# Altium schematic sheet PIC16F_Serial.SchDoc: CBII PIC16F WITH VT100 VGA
size A3; Engineer: SRKH; DocumentNumber: 1; Revision: 1.00; SheetNumber: 1; SheetTotal: 7
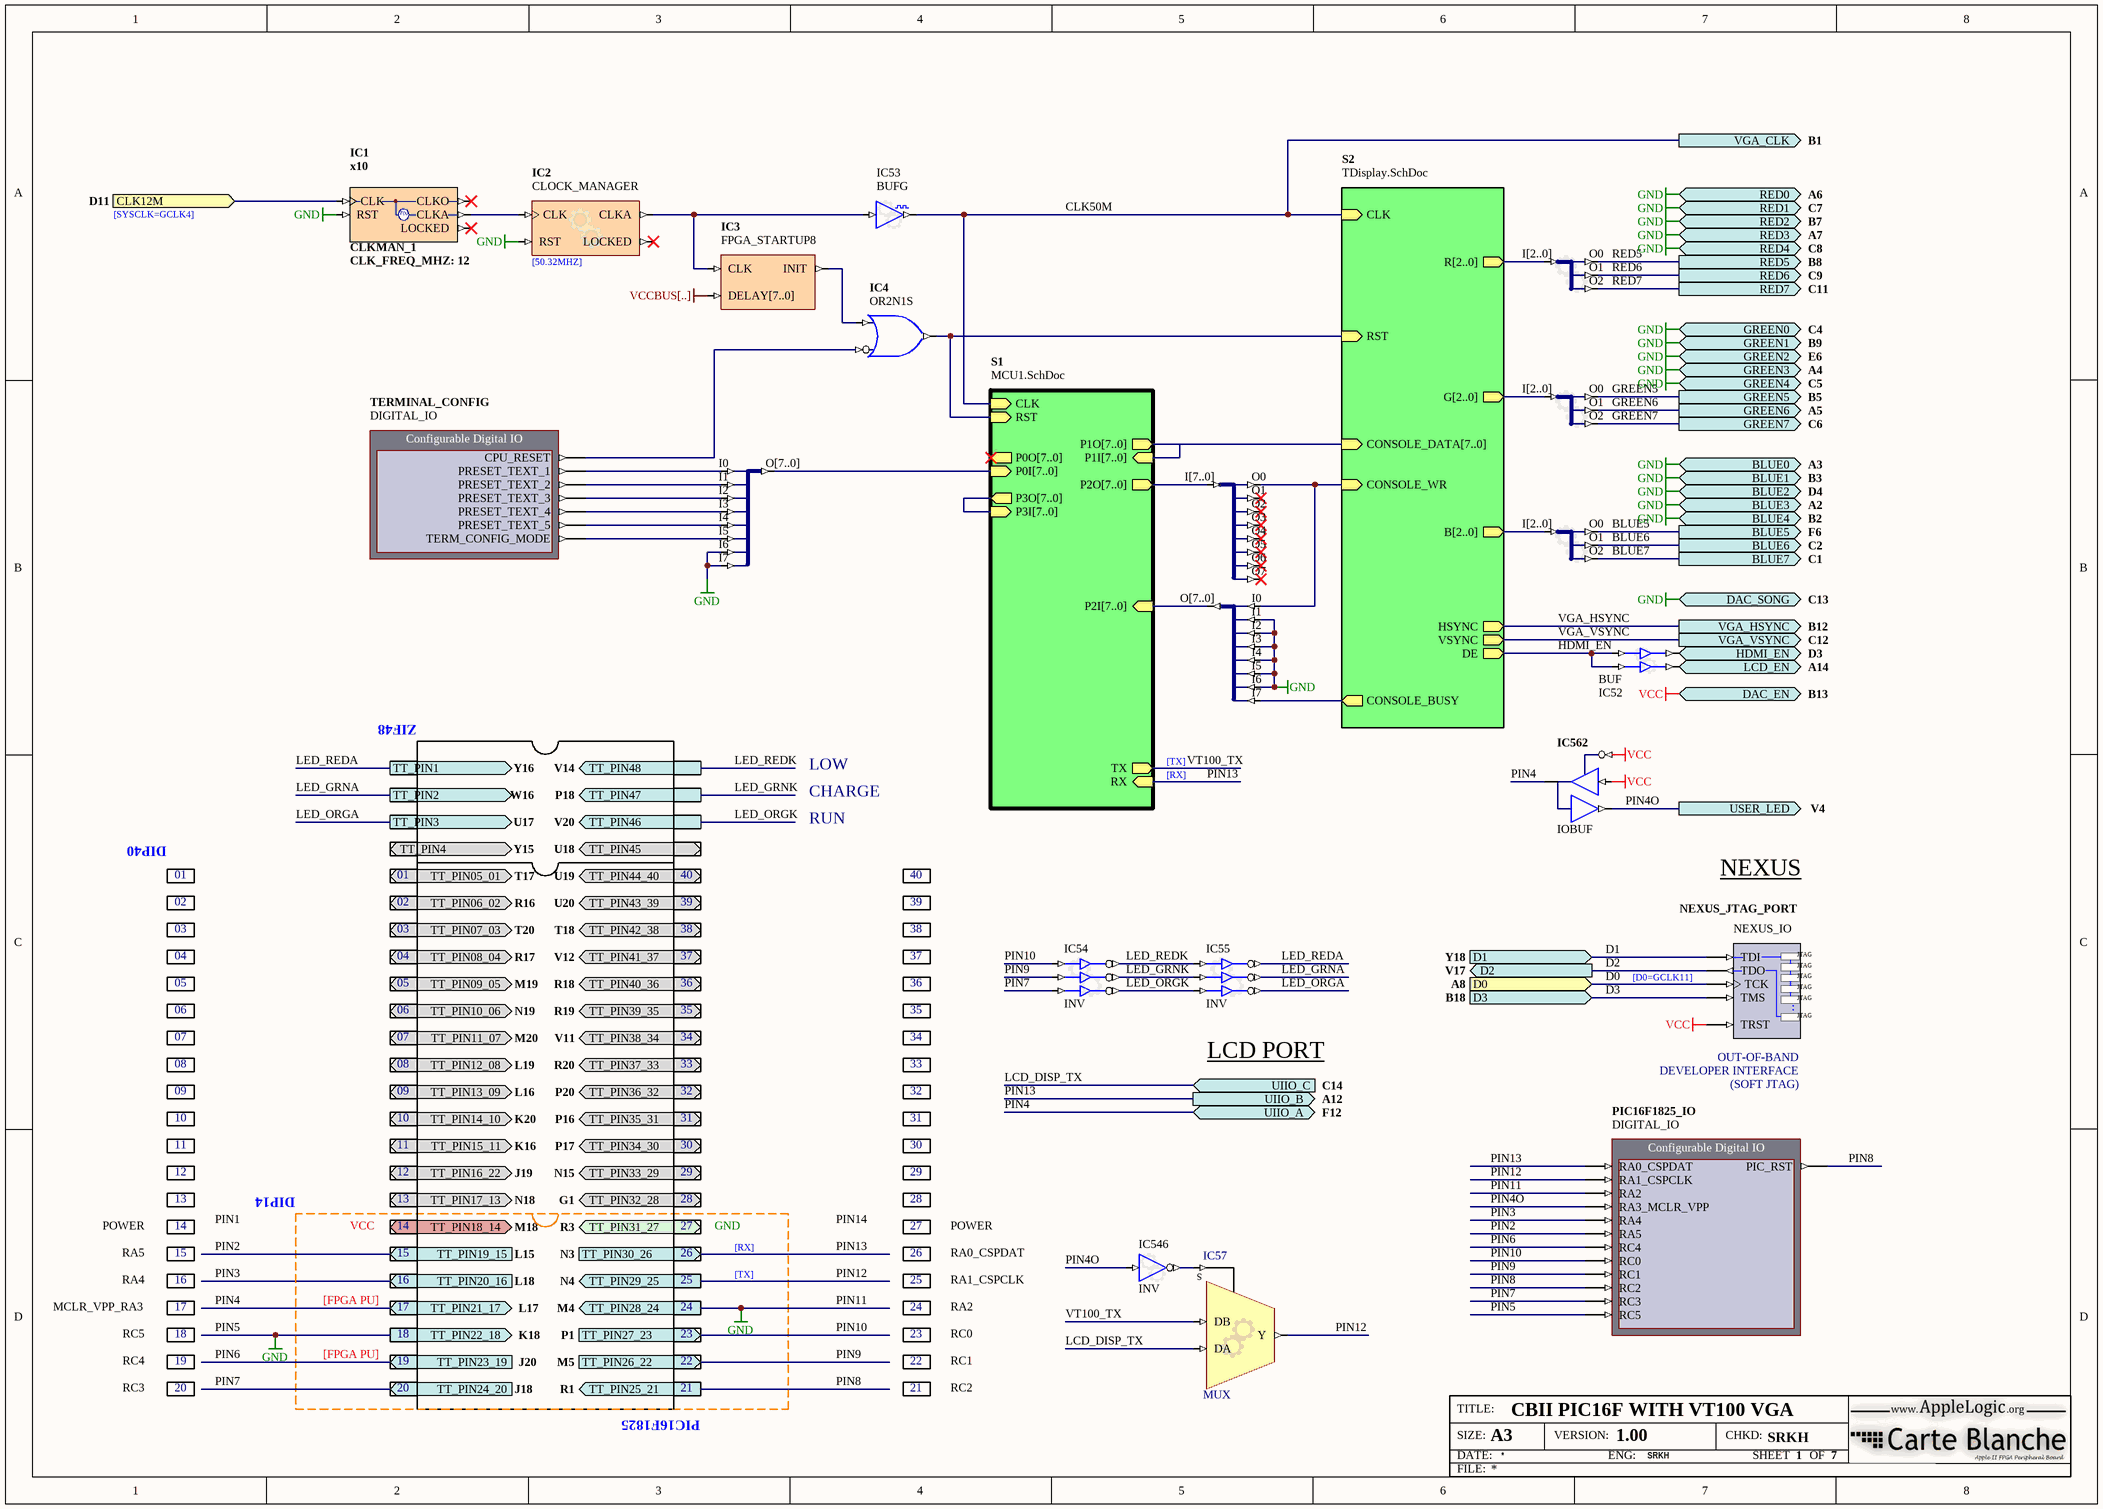
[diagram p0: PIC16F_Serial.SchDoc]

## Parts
IC1  CLKMAN_1  CLK_FREQ_MHZ: 12  ClkA_Operation: x10
IC2  CLOCK_MANAGER
IC3  FPGA_STARTUP8
IC4  OR2N1S
IC5  BUS_JS  (value not drawn)
IC6  BUS_JS  (value not drawn)
IC7  J8B_8S  (value not drawn)
IC8  BUS_JS  (value not drawn)
IC9  J8S_8B  (value not drawn)
IC10  J8S_8B  (value not drawn)
IC52  BUF
IC53  BUFG
IC54  INV
IC55  INV
IC57  MUX
IC546  INV
IC562  IOBUF
NEXUS_JTAG_PORT  NEXUS_IO
PIC16F1825_IO  DIGITAL_IO
TERMINAL_CONFIG  DIGITAL_IO

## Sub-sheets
S1 = MCU1.SchDoc: CLK (in), RST (in), P0O[7..0] (out), P0I[7..0] (in), P1O[7..0] (out), P1I[7..0] (in), P2O[7..0] (out), P2I[7..0] (in), P3O[7..0] (out), P3I[7..0] (in), TX (out), RX (in)
S2 = TDisplay.SchDoc: CLK (in), HSYNC (out), VSYNC (out), R[2..0] (out), G[2..0] (out), B[2..0] (out), CONSOLE_WR (in), CONSOLE_DATA[7..0] (in), CONSOLE_BUSY (out), RST (in), DE (out)

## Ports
BLUE0 (out, see A3), BLUE1 (out, see B3), BLUE2 (out, see D4), BLUE3 (out, see A2), BLUE4 (out, see B2), BLUE5 (out, see F6), BLUE6 (out, see C2), BLUE7 (out, see C1), CLK12M (in, see D11), D0 (in, see A8), D1 (in, see Y18), D2 (out, see V17), D3 (in, see B18), DAC_EN (out, see B13), DAC_SONG (out, see C13), GREEN0 (out, see C4), GREEN1 (out, see B9), GREEN2 (out, see E6), GREEN3 (out, see A4), GREEN4 (out, see C5), GREEN5 (out, see B5), GREEN6 (out, see A5), GREEN7 (out, see C6), HDMI_EN (out, see D3), LCD_EN (out, see A14), RED0 (out, see A6), RED1 (out, see C7), RED2 (out, see B7), RED3 (out, see A7), RED4 (out, see C8), RED5 (out, see B8), RED6 (out, see C9), RED7 (out, see C11), TT_PIN1 (out, see Y16), TT_PIN2 (out, see W16), TT_PIN3 (out, see U17), TT_PIN4 (bidir, see Y15), TT_PIN05_01 (bidir, see T17), TT_PIN06_02 (bidir, see R16), TT_PIN07_03 (bidir, see T20), TT_PIN08_04 (bidir, see R17), TT_PIN09_05 (bidir, see M19), TT_PIN10_06 (bidir, see N19), TT_PIN11_07 (bidir, see M20), TT_PIN12_08 (bidir, see L19), TT_PIN13_09 (bidir, see L16), TT_PIN14_10 (bidir, see K20), TT_PIN15_11 (bidir, see K16), TT_PIN16_22 (bidir, see J19), TT_PIN17_13 (bidir, see N18), TT_PIN18_14 (in, see M18), TT_PIN19_15 (in, see L15), TT_PIN20_16 (in, see L18), TT_PIN21_17 (bidir, see L17), TT_PIN22_18 (out, see K18), TT_PIN23_19 (in, see J20), TT_PIN24_20 (in, see J18), TT_PIN25_21 (out, see R1), TT_PIN26_22 (in, see M5), TT_PIN27_23 (in, see P1), TT_PIN28_24 (out, see M4), TT_PIN29_25 (out, see N4), TT_PIN30_26 (in, see N3), TT_PIN31_27 (in, see R3), TT_PIN32_28 (bidir, see G1), TT_PIN33_29 (bidir, see N15), TT_PIN34_30 (bidir, see P17), TT_PIN35_31 (bidir, see P16), TT_PIN36_32 (bidir, see P20), TT_PIN37_33 (bidir, see R20), TT_PIN38_34 (bidir, see V11), TT_PIN39_35 (bidir, see R19), TT_PIN40_36 (bidir, see R18), TT_PIN41_37 (bidir, see V12), TT_PIN42_38 (bidir, see T18), TT_PIN43_39 (bidir, see U20), TT_PIN44_40 (bidir, see U19), TT_PIN45 (in, see U18), TT_PIN46 (out, see V20), TT_PIN47 (out, see P18), TT_PIN48 (out, see V14), UIIO_A (bidir, see F12), UIIO_B (out, see A12), UIIO_C (in, see C14), USER_LED (out, see V4), VGA_CLK (out, see B1), VGA_HSYNC (out, see B12), VGA_VSYNC (out, see C12)

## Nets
PIN11: IC1.RST IC2.RST IC9.I1 IC9.I2 IC9.I3 IC9.I4 IC9.I5 IC9.I6 IC10.I6 IC10.I7 PIC16F1825_IO.RA2 PIC16F1825_IO.RC5 ; port DAC_SONG, port BLUE2, port BLUE3, port BLUE4, port BLUE0, port BLUE1, port RED2, port RED3, port RED4, port RED0, port RED1, port GREEN2, port GREEN3, port GREEN4, port GREEN0, port GREEN1, port TT_PIN22_18, port TT_PIN28_24  [also labelled GND, PIN5]
VCC: IC562.I IC562.T NEXUS_JTAG_PORT.TRST ; port DAC_EN
VCCBUS[..]: IC3.DELAY[7..0]
BLUE5: IC8.O0 ; port BLUE5
BLUE6: IC8.O1 ; port BLUE6
BLUE7: IC8.O2 ; port BLUE7
CLK12M: IC1.CLK ; port CLK12M
CLK50M: IC53.O ; port VGA_CLK, sheet S1/CLK, sheet S2/CLK
D0: NEXUS_JTAG_PORT.TCK ; port D0
D1: NEXUS_JTAG_PORT.TDI ; port D1
D2: NEXUS_JTAG_PORT.TDO ; port D2
D3: NEXUS_JTAG_PORT.TMS ; port D3
GREEN5: IC6.O0 ; port GREEN5
GREEN6: IC6.O1 ; port GREEN6
GREEN7: IC6.O2 ; port GREEN7
HDMI_EN: IC52.I0 IC52.I1 ; sheet S2/DE
HDMI_EN: IC52.O0 ; port HDMI_EN  [a separate net that carries the same name]
LCD_DISP_TX: IC57.DA ; port UIIO_C
LCD_EN: IC52.O1 ; port LCD_EN
LED_GRNA: IC55.O1 ; port TT_PIN2
LED_GRNK: IC54.O1 IC55.I1 ; port TT_PIN47
LED_ORGA: IC55.O2 ; port TT_PIN3
LED_ORGK: IC54.O2 IC55.I2 ; port TT_PIN46
LED_REDA: IC55.O0 ; port TT_PIN1
LED_REDK: IC54.O0 IC55.I0 ; port TT_PIN48
PIN2: PIC16F1825_IO.RA5 ; port TT_PIN19_15
PIN3: PIC16F1825_IO.RA4 ; port TT_PIN20_16
PIN4: IC562.IO ; port TT_PIN21_17, port UIIO_A
PIN4O: IC546.I IC562.O PIC16F1825_IO.RA3_MCLR_VPP ; port USER_LED
PIN6: PIC16F1825_IO.RC4 ; port TT_PIN23_19
PIN7: IC54.I2 PIC16F1825_IO.RC3 ; port TT_PIN24_20
PIN8: PIC16F1825_IO.PIC_RST PIC16F1825_IO.RC2 ; port TT_PIN25_21
PIN9: IC54.I1 PIC16F1825_IO.RC1 ; port TT_PIN26_22
PIN10: IC54.I0 PIC16F1825_IO.RC0 ; port TT_PIN27_23
PIN12: IC57.Y PIC16F1825_IO.RA1_CSPCLK ; port TT_PIN29_25
PIN13: PIC16F1825_IO.RA0_CSPDAT ; port TT_PIN30_26, port UIIO_B, sheet S1/RX
RED5: IC5.O0 ; port RED5
RED6: IC5.O1 ; port RED6
RED7: IC5.O2 ; port RED7
VGA_HSYNC: port VGA_HSYNC, sheet S2/HSYNC
VGA_VSYNC: port VGA_VSYNC, sheet S2/VSYNC
VT100_TX: IC57.DB ; sheet S1/TX
NetIC1_CLKA: IC1.CLKA IC2.CLK
NetIC2_CLKA: IC2.CLKA IC3.CLK IC53.I
NetIC3_INIT: IC3.INIT IC4.I1
NetIC4_I0: IC4.I0 TERMINAL_CONFIG.CPU_RESET
NetIC4_O: IC4.O ; sheet S1/RST, sheet S2/RST
NetIC7_O0: IC7.O0 IC9.I0 ; sheet S2/CONSOLE_WR
NetIC9_I7: IC9.I7 ; sheet S2/CONSOLE_BUSY
NetIC10_I0: IC10.I0 TERMINAL_CONFIG.PRESET_TEXT_1
NetIC10_I1: IC10.I1 TERMINAL_CONFIG.PRESET_TEXT_2
NetIC10_I2: IC10.I2 TERMINAL_CONFIG.PRESET_TEXT_3
NetIC10_I3: IC10.I3 TERMINAL_CONFIG.PRESET_TEXT_4
NetIC10_I4: IC10.I4 TERMINAL_CONFIG.PRESET_TEXT_5
NetIC10_I5: IC10.I5 TERMINAL_CONFIG.TERM_CONFIG_MODE
NetIC57_S: IC57.S IC546.O

Not connected (* = marked no-connect by the designer): IC1 CLKO* LOCKED*; IC2 LOCKED*; IC5 I[2..0]; IC6 I[2..0]; IC7 I[7..0] O1* O2* O3* O4* O5* O6* O7*; IC8 I[2..0]; IC9 O[7..0]; IC10 O[7..0]

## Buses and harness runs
bus sheet S1/P1I[7..0] = sheet S1/P1O[7..0] = sheet S2/CONSOLE_DATA[7..0]
bus sheet S1/P3I[7..0] = sheet S1/P3O[7..0]

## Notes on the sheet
- [SYSCLK=GCLK4]
- (near IC2) [50.32MHZ]
- ZIF48
- LOW
- [TX]
- [RX]
- DIP40
- RUN
- CHARGE
- 01
- 02
- 40
- 39
- NEXUS
- 03
- 04
- 05
- 38
- 37
- 36
- (near NEXUS_JTAG_PORT) [D0=GCLK11]
- 06
- 07
- 35
- 34
- 08
- 09
- 10
- 33
- 32
- 31
- (near IC55) LCD PORT
- (near NEXUS_JTAG_PORT) DEVELOPER INTERFACE
- (near NEXUS_JTAG_PORT) OUT-OF-BAND
- (SOFT JTAG)
- 11
- 12
- DIP14
- 30
- 29
- POWER
- RA5
- 13
- 14
- 15
- VCC
- 28
- 27
- 26
- GND
- RA0_CSPDAT
- MCLR_VPP_RA3
- RA4
- 16
- 17
- [FPGA PU]
- 25
- 24
- RA1_CSPCLK
- RA2
- RC5
- RC4
- RC3
- 18
- 19
- 20
- 23
- 22
- 21
- RC0
- RC1
- RC2
- PIC16F1825
- Labels drawn without touching a wire or pin: PIN1, PIN14

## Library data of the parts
IC1 = CLKMAN_1: Single Operational Output Clock Manager; Clk_Count: 1
IC2 = CLOCKMANAGER: Configurable Clock Manager; ConfiguratorName: GENERIC_CLOCKMANAGER; ConfigurationParameters: {}Version[1.0]{}Option_Configuration[object _1: TClockManagerPersist / VersionMajor [ 0 / VersionMinor [ 0 / InputFreq [ 120.000000000000000000 / InputName [ 'CLK' / OutputTargets [ < / item / Name [ 'CLKA' / OutFreqMin [ 49.846500000000000000 / OutFreqMax [ 50.853500000000000000 / OutPostDivider [ 1.000000000000000000 / end> / OutputDevices [ < / item / Name [ 'Spartan3AN' / Valid [ True / OutputActuals [ < / item / Name [ 'CLK0' / Multipler [ 1.000000000000000000 / Divider [ 1.000000000000000000 / OutFreq [ 120.000000000000000000 / OutputMap [ 1 / end / item / Name [ 'CLK90' / Multipler [ 1.000000000000000000 / Divider [ 1.000000000000000000 / OutPhase [ 90.000000000000000000 / OutFreq [ 120.000000000000000000 / OutputMap [ 2 / end / item / Name [ 'CLK180' / Multipler [ 1.000000000000000000 / Divider [ 1.000000000000000000 / OutPhase [ 180.000000000000000000 / OutFreq [ 120.000000000000000000 / OutputMap [ 3 / end / item / Name [ 'CLK270' / Multipler [ 1.000000000000000000 / Divider [ 1.000000000000000000 / OutPhase [ 270.000000000000000000 / OutFreq [ 120.000000000000000000 / OutputMap [ 4 / end / item / Name [ 'CLK2X' / Multipler [ 2.000000000000000000 / Divider [ 1.000000000000000000 / OutFreq [ 240.000000000000000000 / OutputMap [ 5 / end / item / Name [ 'CLKDV' / Multipler [ 1.000000000000000000 / Divider [ 16.000000000000000000 / OutFreq [ 7.500000000000000000 / OutputMap [ 6 / end / item / Name [ 'CLK2X180' / Multipler [ 1.000000000000000000 / Divider [ 1.000000000000000000 / OutPhase [ 180.000000000000000000 / OutFreq [ 240.000000000000000000 / OutputMap [ 7 / end / item / Name [ 'CLKFX' / Multipler [ 13.000000000000000000 / Divider [ 31.000000000000000000 / OutFreq [ 50.322580645161290000 / OutputMap [ 0 / end / item / Name [ 'CLKFX180' / Multipler [ 1.000000000000000000 / Divider [ 1.000000000000000000 / OutPhase [ 180.000000000000000000 / OutFreq [ 50.322580645161290000 / OutputMap [ 8 / end> / InternalActuals [ <> / CustomVars [ <> / end> / MinInputFreq [ 1.000000000000000000 / MaxInputFreq [ 280.000000000000000000 / MinOutputFreq [ 18.000000000000000000 / MaxOutputFreq [ 210.000000000000000000 / MaxOutputCount [ 9 / end]{}
IC3 = FPGA_STARTUP8: FPGA Startup With 8 Bit Delay
IC4 = OR2N1S: 2-Input OR Gate with Active Low A Input, Single Pin Version; Xilinx Equivalent: OR2B1; ArchiveName: GENERIC
IC5 IC6 IC8 = BUS_JS: Configurable Bus Joiner/Splitter; ConfiguratorName: GENERIC_BUS_JS; ConfigurationParameters: {}Version[1.1]{}SplitterJoinerType[Splitter]{}SignalCount[3]{}SignalWidth0[1]{}GapBelow0[1000000]{}ConnectionType0[Pin]{}SignalWidth1[1]{}GapBelow1[1000000]{}ConnectionType1[Pin]{}SignalWidth2[1]{}GapBelow2[1000000]{}ConnectionType2[Pin]{}ShowPinNames[True]{}
IC7 = J8B_8S: 8-Bit input bus to 8 single pin outputs; FunctionalClass: Bus Joiner; PortSize: 8; ArchiveName: GENERIC; VHDLIB_SIM: GENERIC_LIB
IC9 = J8S_8B: 8 Single pin inputs to single 8-Bit output bus; FunctionalClass: Bus Joiner; PortSize: 8; ArchiveName: GENERIC; VHDLIB_SIM: GENERIC_LIB
IC10 = J8S_8B: 8 Single pin inputs to single 8-Bit output bus; ArchiveName: GENERIC; VHDLIB_SIM: GENERIC_LIB
IC52 = BUF: Configurable Buffer; ConfiguratorName: GENERIC_BUFFER; ConfigurationParameters: {}Version[1.1]{}SignalCount[2]{}SignalWidth0[1]{}OutputOption0[Normal]{}SignalWidth1[1]{}OutputOption1[Normal]{}EnableMode[None]{}ShowPinNames[False]{}
IC53 = BUFG: Configurable Global Clock Buffer; ConfiguratorName: GENERIC_BUFFER; ConfigurationParameters: {}Version[1.1]{}SignalCount[1]{}SignalWidth0[1]{}OutputOption0[Global Clock]{}EnableMode[None]{}ShowPinNames[False]{}
IC54 IC55 = INV: Configurable Inverter; ConfiguratorName: GENERIC_BUFFER; ConfigurationParameters: {}Version[1.1]{}SignalCount[3]{}SignalWidth0[1]{}OutputOption0[Inverted]{}SignalWidth1[1]{}OutputOption1[Inverted]{}SignalWidth2[1]{}OutputOption2[Inverted]{}EnableMode[None]{}ShowPinNames[False]{}
IC57 = MUX: Configurable Mutliplexer; ConfigurationParameters: {}Version[1.0]{}ShowEnable[False]{}BusInputs[False]{}BusOutputs[False]{}SignalWidth[1]{}Type[Multiplexer]{}RegisterOutputs[False]{}NegativeClockEdge[False]{}ShowPinNames[True]{}InvertSingleSignal[False]{}SignalCount[2]{}Invert0[False]{}Invert1[False]{}; ConfiguratorName: GENERIC_MULTIPLEXER
IC546 = INV: Configurable Inverter; ConfiguratorName: GENERIC_BUFFER; ConfigurationParameters: {}Version[1.1]{}SignalCount[1]{}SignalWidth0[1]{}OutputOption0[Inverted]{}EnableMode[None]{}ShowPinNames[False]{}
IC562 = IOBUF: Input/Output Buffer; Enable: Low; Control: Common Control T; ArchiveName: GENERIC; VHDLIB_SIM: GENERIC_LIB
NEXUS_JTAG_PORT = NEXUS_JTAG_PORT: Soft Nexus-Chain Connector; NEXUS_JTAG_CONNECTOR: True
PIC16F1825_IO = DIGITAL_IO: Configurable Digital IO; NEXUS_CORE: Instrument; NEXUS_JTAG_DEVICE: True; NEXUS_JTAG_ORDER: 0; ConfigurationParameters: {}Version[2.0]{}StorageType[3]{}InterfaceType[Parallel]{}SchCompWidth[140]{}Input0Name[RA0_CSPDAT]{}Input0Width[1]{}Input0InitValue[0]{}Input0Kind[LEDs]{}Input0LEDStyle[Red]{}Input1Name[RA1_CSPCLK]{}Input1Width[1]{}Input1InitValue[0]{}Input1Kind[LEDs]{}Input1LEDStyle[Red]{}Input2Name[RA2]{}Input2Width[1]{}Input2InitValue[0]{}Input2Kind[LEDs]{}Input2LEDStyle[Red]{}Input3Name[RA3_MCLR_VPP]{}Input3Width[1]{}Input3InitValue[0]{}Input3Kind[LEDs]{}Input3LEDStyle[Red]{}Input4Name[RA4]{}Input4Width[1]{}Input4InitValue[0]{}Input4Kind[LEDs]{}Input4LEDStyle[Red]{}Input5Name[RA5]{}Input5Width[1]{}Input5InitValue[0]{}Input5Kind[LEDs]{}Input5LEDStyle[Red]{}Input6Name[RC4]{}Input6Width[1]{}Input6InitValue[0]{}Input6Kind[LEDs]{}Input6LEDStyle[Red]{}Input7Name[RC0]{}Input7Width[1]{}Input7InitValue[0]{}Input7Kind[LEDs]{}Input7LEDStyle[Red]{}Input8Name[RC1]{}Input8Width[1]{}Input8InitValue[0]{}Input8Kind[LEDs]{}Input8LEDStyle[Red]{}Input9Name[RC2]{}Input9Width[1]{}Input9InitValue[0]{}Input9Kind[LEDs]{}Input9LEDStyle[Red]{}Input10Name[RC3]{}Input10Width[1]{}Input10InitValue[0]{}Input10Kind[LEDs]{}Input10LEDStyle[Red]{}Input11Name[RC5]{}Input11Width[1]{}Input11InitValue[0]{}Input11Kind[LEDs]{}Input11LEDStyle[Red]{}Output0Name[PIC_RST]{}Output0Width[1]{}Output0InitValue[15]{}Output0Kind[Numeric]{}Output0NumRadix[Binary]{}Designator[PIC16F1825_IO]{}InternalID[0]{}
TERMINAL_CONFIG = DIGITAL_IO: Configurable Digital IO; NEXUS_CORE: Instrument; NEXUS_JTAG_DEVICE: True; NEXUS_JTAG_ORDER: 0; ConfigurationParameters: {}Version[2.0]{}StorageType[3]{}InterfaceType[Parallel]{}SchCompWidth[140]{}NoInputs[ ]{}Output0Name[CPU_RESET]{}Output0Width[1]{}Output0InitValue[1]{}Output0Kind[Numeric]{}Output0NumRadix[Binary]{}Output1Name[PRESET_TEXT_1]{}Output1Width[1]{}Output1InitValue[1]{}Output1Kind[Numeric]{}Output1NumRadix[Binary]{}Output2Name[PRESET_TEXT_2]{}Output2Width[1]{}Output2InitValue[1]{}Output2Kind[Numeric]{}Output2NumRadix[Binary]{}Output3Name[PRESET_TEXT_3]{}Output3Width[1]{}Output3InitValue[1]{}Output3Kind[Numeric]{}Output3NumRadix[Binary]{}Output4Name[PRESET_TEXT_4]{}Output4Width[1]{}Output4InitValue[1]{}Output4Kind[Numeric]{}Output4NumRadix[Binary]{}Output5Name[PRESET_TEXT_5]{}Output5Width[1]{}Output5InitValue[1]{}Output5Kind[Numeric]{}Output5NumRadix[Binary]{}Output6Name[TERM_CONFIG_MODE]{}Output6Width[1]{}Output6InitValue[1]{}Output6Kind[Numeric]{}Output6NumRadix[Binary]{}Designator[SEL_SW]{}InternalID[1]{}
